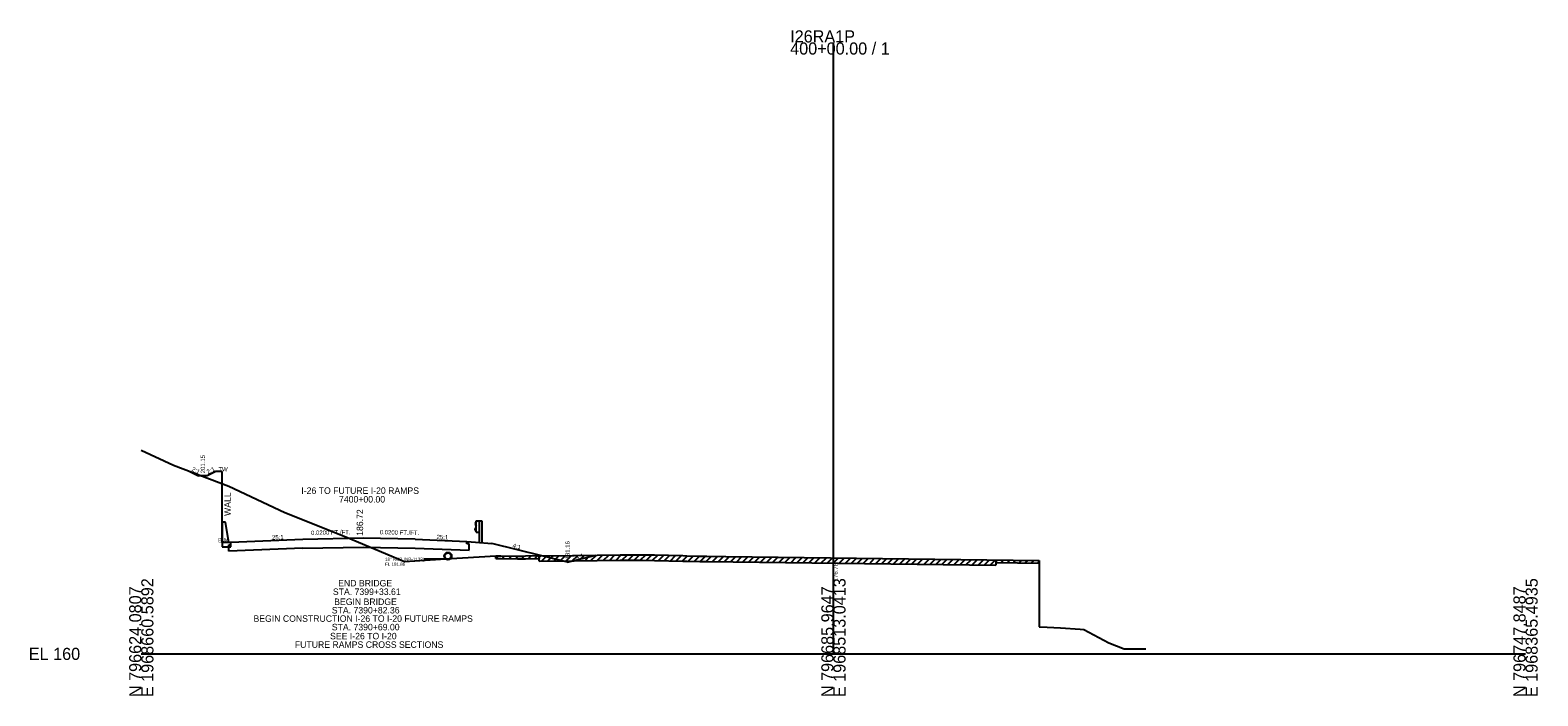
# Model space of a CAD drawing. Extents: x -44 to 4323, y -10 to 9601.
# Drawn here: x -25.7 to 322.8, y -9.7 to 144.1 of the extents above; entities that cross this region are included whole.
import ezdxf

# ---------------------------------------------------------------- set-up
doc = ezdxf.new("R2010")
doc.units = 0
for name, color, linetype in [('1', 7, 'Continuous'), ('DateStamp', 7, 'Continuous'), ('NotForConst', 7, 'Continuous'), ('RD_SHT_Bndy', 7, 'Continuous'), ('RD_SHT_Iplotshp', 7, 'Continuous'), ('RD_SHT_TX', 7, 'Continuous'), ('RD_Sketch10', 7, 'Continuous'), ('RD_XS_Base', 7, 'Continuous'), ('RD_XS_ExGround', 7, 'Continuous'), ('RD_XS_ExPaveRet', 7, 'Continuous'), ('RD_XS_MatchLine', 7, 'Continuous'), ('RD_XS_Misc_Line', 7, 'Continuous'), ('RD_XS_Pave', 7, 'Continuous'), ('RD_XS_PaveShd', 7, 'Continuous'), ('RD_XS_Pipe', 7, 'Continuous'), ('RD_XS_TX_Elev_PR', 7, 'Continuous'), ('RD_XS_TX_ShdSlope', 7, 'Continuous'), ('RD_XS_TX_Slope', 7, 'Continuous'), ('seal', 7, 'Continuous'), ('TR SN EXTRUDED PANEL SIGNS - GROUND MOUNTED', 7, 'Continuous')]:
    doc.layers.add(name, color=color, linetype=linetype)

msp = doc.modelspace()

# ---------------------------------------------------------------- linework, layer by layer
at = {"layer": 'DateStamp'}
for p, q in [((129.13, 22.59), (207.56, 21.6)), ((207.56, 21.6), (207.56, 6.23))]:
    msp.add_line(p, q, dxfattribs=at)
for points in [[(0, 47.09), (7.41, 43.6), (20.25, 38.72), (33.17, 32.64), (47.26, 27.03), (60.83, 21.38), (70.41, 21.95), (81.96, 22.69), (83.09, 22.67), (86.94, 22.58), (88.2, 22.61), (88.79, 22.62), (99.7, 22.73), (100.03, 22.74), (110.67, 22.88), (111.67, 22.89), (112.6, 22.89), (113.52, 22.89), (115.07, 22.87), (115.89, 22.9), (118.6, 22.86), (125.17, 22.7), (126.09, 22.67), (129.13, 22.59), (130.29, 22.57), (130.77, 22.57)], [(207.56, 6.23), (209.4, 6.18), (212.47, 5.99), (217.04, 5.72), (217.87, 5.65), (223.65, 2.57), (227.22, 1.2), (227.7, 1.2), (232.18, 1.2)]]:
    msp.add_lwpolyline(points, dxfattribs=at)
at = {"layer": 'NotForConst'}
for p, q in [((81.96, 22.06), (82.57, 22.68)), ((83.46, 22.04), (84.07, 22.65)), ((84.96, 22), (85.58, 22.61)), ((86.47, 21.97), (87.09, 22.58)), ((87.97, 21.98), (88.61, 22.62)), ((89.47, 22), (90.11, 22.64)), ((90.98, 22.02), (91.61, 22.65)), ((91.98, 22.31), (92.33, 22.66)), ((92.49, 21.41), (93.76, 22.67)), ((93.92, 21.42), (95.18, 22.69)), ((95.35, 21.44), (96.61, 22.7)), ((96.78, 21.45), (98.04, 22.72)), ((98.21, 21.47), (99.47, 22.73)), ((99.64, 21.48), (100.9, 22.75)), ((101.07, 21.5), (102.34, 22.77)), ((102.5, 21.52), (103.77, 22.79)), ((103.94, 21.54), (105.2, 22.8)), ((105.37, 21.56), (106.63, 22.82)), ((106.8, 21.58), (108.07, 22.84)), ((108.23, 21.59), (109.5, 22.86)), ((109.67, 21.61), (110.93, 22.88)), ((111.1, 21.63), (112.36, 22.89)), ((112.52, 21.64), (113.77, 22.89)), ((113.93, 21.64), (115.17, 22.87)), ((115.34, 21.63), (116.6, 22.89)), ((116.77, 21.64), (118, 22.87)), ((118.16, 21.62), (119.38, 22.84)), ((119.54, 21.59), (120.76, 22.81)), ((120.92, 21.55), (122.14, 22.77)), ((122.3, 21.52), (123.52, 22.74)), ((123.68, 21.48), (124.9, 22.7)), ((125.06, 21.45), (126.27, 22.66)), ((126.43, 21.41), (127.65, 22.63)), ((127.81, 21.37), (129.03, 22.59)), ((129.19, 21.34), (130.42, 22.57)), ((130.58, 21.32), (131.82, 22.55)), ((131.98, 21.3), (133.22, 22.54)), ((133.38, 21.28), (134.61, 22.52)), ((134.78, 21.27), (136.01, 22.5)), ((136.17, 21.25), (137.41, 22.48)), ((137.57, 21.23), (138.8, 22.47)), ((138.97, 21.21), (140.2, 22.45)), ((140.36, 21.2), (141.6, 22.43)), ((141.76, 21.18), (142.99, 22.41)), ((143.16, 21.16), (144.39, 22.4)), ((144.55, 21.14), (145.79, 22.38)), ((145.95, 21.13), (147.18, 22.36)), ((147.35, 21.11), (148.58, 22.34)), ((148.74, 21.09), (149.98, 22.32)), ((150.14, 21.07), (151.37, 22.31)), ((151.54, 21.06), (152.77, 22.29)), ((152.93, 21.04), (154.17, 22.27)), ((154.33, 21.02), (155.56, 22.25)), ((155.73, 21), (156.96, 22.24)), ((157.12, 20.99), (158.36, 22.22)), ((158.52, 20.97), (159.75, 22.2)), ((159.92, 20.95), (161.15, 22.18)), ((161.31, 20.93), (162.55, 22.17)), ((162.71, 20.91), (163.94, 22.15)), ((164.11, 20.9), (165.34, 22.13)), ((165.5, 20.88), (166.74, 22.11)), ((166.9, 20.86), (168.13, 22.1)), ((168.3, 20.84), (169.53, 22.08)), ((169.69, 20.83), (170.93, 22.06)), ((171.09, 20.81), (172.32, 22.04)), ((172.49, 20.79), (173.72, 22.03)), ((173.88, 20.77), (175.12, 22.01)), ((175.28, 20.76), (176.51, 21.99)), ((176.68, 20.74), (177.91, 21.97)), ((178.07, 20.72), (179.31, 21.96)), ((179.47, 20.7), (180.7, 21.94)), ((180.87, 20.69), (182.1, 21.92)), ((182.26, 20.67), (183.5, 21.9)), ((183.66, 20.65), (184.89, 21.89)), ((185.06, 20.63), (186.29, 21.87)), ((186.45, 20.62), (187.69, 21.85)), ((187.85, 20.6), (189.08, 21.83)), ((189.25, 20.58), (190.48, 21.82)), ((190.64, 20.56), (191.88, 21.8)), ((192.04, 20.55), (193.27, 21.78)), ((193.44, 20.53), (194.67, 21.76)), ((194.83, 20.51), (196.07, 21.75)), ((196.23, 20.49), (197.46, 21.73)), ((197.56, 21.29), (197.99, 21.72)), ((198.77, 21.09), (199.39, 21.7)), ((200.17, 21.07), (200.79, 21.69)), ((201.57, 21.05), (202.18, 21.67)), ((202.96, 21.03), (203.58, 21.65)), ((204.36, 21.02), (204.98, 21.63)), ((205.76, 21), (206.37, 21.62)), ((207.15, 20.98), (207.56, 21.39))]:
    msp.add_line(p, q, dxfattribs=at)
at = {"layer": 'RD_SHT_Bndy'}
for p, q in [((160, 0), (160, 141.28)), ((0, 0), (160, 0)), ((160, 0), (320, 0))]:
    msp.add_line(p, q, dxfattribs=at)
at = {"layer": 'RD_SHT_Iplotshp'}
for p, q in [((81.96, 22.06), (81.96, 22.69)), ((81.96, 22.06), (83.09, 22.04)), ((83.09, 22.04), (86.94, 21.96)), ((86.94, 21.96), (88.2, 21.98)), ((88.2, 21.98), (88.79, 22)), ((88.79, 22), (91.98, 22.03)), ((91.98, 21.4), (91.98, 22.65)), ((91.98, 22.65), (91.98, 22.03)), ((91.98, 21.4), (99.7, 21.48)), ((99.7, 21.48), (100.03, 21.49)), ((100.03, 21.49), (110.67, 21.63)), ((110.67, 21.63), (111.67, 21.64)), ((111.67, 21.64), (112.6, 21.64)), ((112.6, 21.64), (113.52, 21.64)), ((113.52, 21.64), (115.07, 21.62)), ((115.07, 21.62), (115.89, 21.65)), ((115.89, 21.65), (118.6, 21.61)), ((118.6, 21.61), (125.17, 21.45)), ((125.17, 21.45), (126.09, 21.42)), ((126.09, 21.42), (129.13, 21.34)), ((129.13, 21.34), (130.29, 21.32)), ((130.29, 21.32), (130.77, 21.32)), ((130.76, 21.32), (197.56, 20.48)), ((197.56, 21.73), (197.56, 20.48)), ((197.56, 21.1), (207.56, 20.98)), ((207.56, 20.98), (207.56, 21.6))]:
    msp.add_line(p, q, dxfattribs=at)
at = {"layer": 'RD_XS_Base'}
for p, q in [((77.43, 30.55), (77.16, 30.11)), ((77.16, 30.11), (77.16, 30)), ((77.16, 30), (77.43, 29.56)), ((77.16, 28.85), (77.43, 29.29)), ((77.16, 28.74), (77.16, 28.85)), ((77.43, 28.3), (77.16, 28.74)), ((77.43, 30.71), (78.1, 30.71)), ((77.43, 28.14), (77.43, 30.71)), ((77.43, 28.14), (78.1, 28.14)), ((78.1, 30.71), (78.76, 30.71)), ((78.1, 30.71), (78.1, 25.77)), ((78.76, 30.71), (78.76, 25.66))]:
    msp.add_line(p, q, dxfattribs=at)
at = {"layer": 'RD_XS_ExPaveRet'}
for p, q in [((18.73, 25.77), (18.73, 42.15)), ((20.73, 25.77), (18.73, 25.77))]:
    msp.add_line(p, q, dxfattribs=at)
at = {"layer": 'RD_XS_Misc_Line'}
for p, q in [((20.23, 25.19), (20.73, 25.21)), ((20.23, 23.71), (20.23, 25.19)), ((20.73, 25.21), (20.73, 25.77)), ((37.31, 24.4), (51.28, 24.68)), ((51.28, 24.68), (63.28, 24.44)), ((63.28, 24.44), (75.78, 23.94)), ((75.28, 25.44), (75.28, 26)), ((75.78, 25.42), (75.28, 25.44)), ((75.78, 23.94), (75.78, 25.42)), ((37.31, 24.4), (20.23, 23.71))]:
    msp.add_line(p, q, dxfattribs=at)
at = {"layer": 'RD_XS_Pave'}
for p, q in [((77.28, 25.84), (81.03, 25.54)), ((98.54, 21.16), (81.03, 25.54)), ((98.54, 21.16), (105.11, 22.8))]:
    msp.add_line(p, q, dxfattribs=at)
at = {"layer": 'RD_XS_PaveShd'}
for p, q in [((11.23, 42.15), (13.23, 41.15)), ((17.23, 42.15), (15.23, 41.15)), ((18.73, 42.15), (17.23, 42.15)), ((15.23, 41.15), (13.23, 41.15)), ((75.28, 26), (77.28, 25.84))]:
    msp.add_line(p, q, dxfattribs=at)
at = {"layer": 'RD_XS_Pipe'}
msp.add_line((70.39, 21.86), (65.39, 21.86), dxfattribs=at)
for radius in [0.85, 0.75]:
    msp.add_circle((70.89, 22.61), radius, dxfattribs=at)
at = {"layer": 'RD_XS_TX_Elev_PR'}
for p, q in [((37.31, 26.44), (20.73, 25.77)), ((63.28, 26.48), (75.28, 26))]:
    msp.add_line(p, q, dxfattribs=at)
at = {"layer": 'RD_XS_TX_ShdSlope'}
for p, q in [((19.48, 30.44), (18.73, 30.44)), ((18.73, 30.44), (18.73, 24.77)), ((20.23, 25.77), (19.48, 30.44)), ((18.73, 24.77), (20.73, 24.77)), ((20.73, 25.77), (20.23, 25.77)), ((20.73, 24.77), (20.73, 25.77))]:
    msp.add_line(p, q, dxfattribs=at)
at = {"layer": 'RD_XS_TX_Slope'}
for p, q in [((51.28, 26.72), (37.31, 26.44)), ((63.28, 26.48), (51.28, 26.72))]:
    msp.add_line(p, q, dxfattribs=at)

# ---------------------------------------------------------------- texts
at = {"layer": '1'}
for s, p in [('I-26 TO FUTURE I-20 RAMPS', (37, 36.97)), ('7400+00.00', (45.71, 34.97))]:
    msp.add_text(s, height=1.5, dxfattribs=at).set_placement(p)
at = {"layer": 'RD_SHT_Bndy'}
for s, p in [('I26RA1P', (150, 141.28)), ('400+00.00 / 1', (150, 138.48)), ('EL 160', (-26, -1.4))]:
    msp.add_text(s, height=2.8, dxfattribs=at).set_placement(p)
for s, p in [('N 796624.0807', (0, -10)), ('E 1968660.5892', (2.8, -10)), ('N 796685.9647', (160, -10)), ('E 1968513.0413', (162.8, -10)), ('N 796747.8487', (320, -10)), ('E 1968365.4935', (322.8, -10))]:
    msp.add_text(s, height=2.8, rotation=90, dxfattribs=at).set_placement(p)
at = {"layer": 'RD_SHT_TX'}
msp.add_text('176.78', height=1, rotation=90, dxfattribs=at).set_placement((161, 16.78))
at = {"layer": 'RD_Sketch10'}
for s, p in [('TW', (17.82, 42.15)), ('BW', (17.75, 25.77))]:
    msp.add_text(s, height=1, dxfattribs=at).set_placement(p)
at = {"layer": 'RD_XS_ExGround'}
for rotation, p in [(2.2888, (30.24, 26.4)), (357.7094, (68.24, 26.53))]:
    msp.add_text('25:1', height=1, rotation=rotation, dxfattribs=at).set_placement(p)
at = {"layer": 'RD_XS_MatchLine'}
msp.add_text('WALL', height=1.5, rotation=90, dxfattribs=at).set_placement((20.67, 31.87))
for s, p in [('STA. 7399+33.61', (44.29, 13.61)), ('END BRIDGE', (45.51, 15.58)), ('STA. 7390+82.36', (44.04, 9.34)), ('BEGIN BRIDGE', (44.59, 11.3)), ('BEGIN CONSTRUCTION I-26 TO I-20 FUTURE RAMPS', (25.93, 7.41)), ('SEE I-26 TO I-20', (43.64, 3.36)), ('STA. 7390+69.00', (44.04, 5.44)), ('FUTURE RAMPS CROSS SECTIONS', (35.5, 1.39))]:
    msp.add_text(s, height=1.5, dxfattribs=at).set_placement(p)
at = {"layer": 'RD_XS_Pipe'}
for s, p in [('18" RCP (NP-1133)', (56.35, 21.48)), ('FL 181.86', (56.35, 20.36))]:
    msp.add_text(s, height=0.75, dxfattribs=at).set_placement(p)
at = {"layer": 'seal'}
msp.add_text(' 186.72', height=1.5, rotation=90, dxfattribs=at).set_placement((51.28, 26.72))
at = {"layer": 'TR SN EXTRUDED PANEL SIGNS - GROUND MOUNTED'}
for s, rotation, p in [('201.15', 90, (14.73, 41.73)), ('2:1', 333.4349, (11.54, 42.36)), ('2:1', 26.5651, (15.42, 41.53)), ('0.0200 FT./FT.', 1.1448, (39.25, 27.48)), ('0.0200 FT./FT.', 358.8542, (55.11, 27.64)), ('4:1', 345.9638, (85.77, 24.6)), ('181.16', 90, (99.04, 21.83)), ('4:1', 14.0362, (100.52, 21.81))]:
    msp.add_text(s, height=1, rotation=rotation, dxfattribs=at).set_placement(p)

doc.saveas('drawing.dxf')
